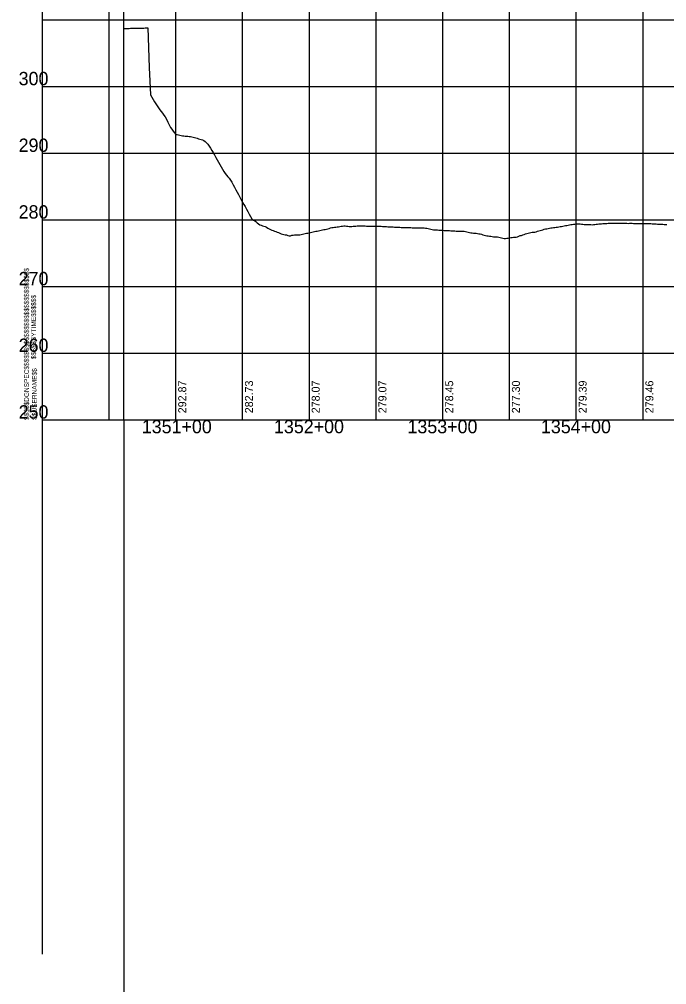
# Model space of a CAD drawing. Extents: x -90830 to 2015517, y -20856 to 836331.
# Drawn here: x 4806 to 5291, y 33228 to 33952 of the extents above; entities that cross this region are included whole.
import ezdxf

# ---------------------------------------------------------------- set-up
doc = ezdxf.new("R2010")
doc.units = 0
for name, color, linetype in [('Level 1', 7, 'Continuous'), ('RD_DDB_ElevTX', 7, 'Continuous'), ('RD_DDB_Profile_EX', 7, 'Continuous'), ('RD_DDB_StaTX', 7, 'Continuous'), ('RD_DDB_StripGrade', 7, 'Continuous'), ('RD_GPK_Profile_Cell', 7, 'Continuous'), ('RD_SHT_MatchLine', 7, 'Continuous')]:
    doc.layers.add(name, color=color, linetype=linetype)

msp = doc.modelspace()

# ---------------------------------------------------------------- linework, layer by layer
at = {"layer": 'Level 1'}
for p, q in [((4823.46, 34151.28), (4823.46, 33651.28)), ((4873.46, 34151.28), (4873.46, 33651.28)), ((4923.46, 34151.28), (4923.46, 33651.28)), ((4973.46, 34151.28), (4973.46, 33651.28)), ((5023.46, 34151.28), (5023.46, 33651.28)), ((5073.46, 34151.28), (5073.46, 33651.28)), ((5123.46, 34151.28), (5123.46, 33651.28)), ((5173.46, 34151.28), (5173.46, 33651.28)), ((5223.46, 34151.28), (5223.46, 33651.28)), ((5273.46, 34151.28), (5273.46, 33651.28)), ((4823.46, 33951.28), (6423.46, 33951.28)), ((4823.46, 33901.28), (6423.46, 33901.28)), ((4823.46, 33851.28), (6423.46, 33851.28)), ((4823.46, 33801.28), (6423.46, 33801.28)), ((4823.46, 33751.28), (6423.46, 33751.28)), ((4823.46, 33701.28), (6423.46, 33701.28)), ((4823.46, 33651.28), (6423.46, 33651.28))]:
    msp.add_line(p, q, dxfattribs=at)
at = {"layer": 'RD_DDB_Profile_EX'}
for points in [[(4884.61, 33944.87), (4885.61, 33944.87), (4886.61, 33944.87), (4887.61, 33944.92), (4888.61, 33944.93), (4889.61, 33944.97), (4890.61, 33945.03), (4891.61, 33945.03), (4892.61, 33945.04), (4893.61, 33945.08), (4894.61, 33945.13), (4895.61, 33945.14), (4896.61, 33945.09), (4897.61, 33945.09), (4898.61, 33945.14), (4899.61, 33945.15), (4900.61, 33945.23), (4901.61, 33945.38), (4902.61, 33945.39), (4903.61, 33915.46), (4904.61, 33895.18), (4905.61, 33893.4), (4906.61, 33891.62), (4907.61, 33889.84), (4908.61, 33888.27), (4909.61, 33886.77), (4910.61, 33885.28), (4911.61, 33883.78), (4912.61, 33882.55), (4913.61, 33881.33), (4914.61, 33879.94), (4915.61, 33878.56), (4916.61, 33876.73), (4917.61, 33874.56), (4918.61, 33872.51), (4919.61, 33870.69), (4920.61, 33869.21), (4921.61, 33867.93), (4922.61, 33866.66), (4923.61, 33865.45), (4924.61, 33865.25), (4925.61, 33865.05), (4926.61, 33864.84), (4927.61, 33864.64), (4928.61, 33864.43), (4929.61, 33864.3), (4930.61, 33864.19), (4931.61, 33864.08), (4932.61, 33863.99), (4933.61, 33863.91), (4934.61, 33863.79), (4935.61, 33863.66), (4936.61, 33863.41), (4937.61, 33863.1), (4938.61, 33862.79), (4939.61, 33862.49), (4940.61, 33862.19), (4941.61, 33861.89), (4942.61, 33861.59), (4943.61, 33861.28), (4944.61, 33860.91), (4945.61, 33859.97), (4946.61, 33859.03), (4947.61, 33858.09), (4948.61, 33856.68), (4949.61, 33855.08), (4950.61, 33853.43), (4951.61, 33851.77), (4952.61, 33850.01), (4953.61, 33848.2), (4954.61, 33846.39), (4955.61, 33844.62), (4956.61, 33842.87), (4957.61, 33841.13), (4958.61, 33839.38), (4959.61, 33837.59), (4960.61, 33836.04), (4961.61, 33834.87), (4962.61, 33833.69), (4963.61, 33832.52), (4964.61, 33831.1), (4965.61, 33829.46), (4966.61, 33827.6), (4967.61, 33825.73), (4968.61, 33823.93), (4969.61, 33822.16), (4970.61, 33820.39), (4971.61, 33818.3), (4972.61, 33816.4), (4973.61, 33814.67), (4974.61, 33812.94), (4975.61, 33811.21), (4976.61, 33809.38), (4977.61, 33807.52), (4978.61, 33805.69), (4979.61, 33803.87), (4980.61, 33802.07), (4981.61, 33801.19), (4982.61, 33800.8), (4983.61, 33799.97), (4984.61, 33799.14)], [(4984.61, 33799.14), (4985.61, 33798.31), (4986.61, 33797.68), (4987.61, 33797.32), (4988.61, 33796.95), (4989.61, 33796.59), (4990.61, 33796.26), (4991.61, 33795.83), (4992.61, 33795.13), (4993.61, 33794.65), (4994.61, 33794.17), (4995.61, 33793.69), (4996.61, 33793.23), (4997.61, 33792.86), (4998.61, 33792.49), (4999.61, 33792.11), (5000.61, 33791.73), (5001.61, 33791.29), (5002.61, 33790.96), (5003.61, 33790.69), (5004.61, 33790.44), (5005.61, 33790.2), (5006.61, 33789.97), (5007.61, 33789.65), (5008.61, 33789.31), (5009.61, 33789.42), (5010.61, 33789.94), (5011.61, 33789.96), (5012.61, 33789.98), (5013.61, 33790.01), (5014.61, 33790.03), (5015.61, 33790.05), (5016.61, 33790.13), (5017.61, 33790.35), (5018.61, 33790.57), (5019.61, 33790.79), (5020.61, 33791.01), (5021.61, 33791.22), (5022.61, 33791.44), (5023.61, 33791.66), (5024.61, 33791.88), (5025.61, 33792.09), (5026.61, 33792.31), (5027.61, 33792.53), (5028.61, 33792.74), (5029.61, 33792.96), (5030.61, 33793.18), (5031.61, 33793.39), (5032.61, 33793.61), (5033.61, 33793.83), (5034.61, 33794.01), (5035.61, 33794.2), (5036.61, 33794.45), (5037.61, 33794.71), (5038.61, 33794.96), (5039.61, 33795.22), (5040.61, 33795.48), (5041.61, 33795.65), (5042.61, 33795.74), (5043.61, 33795.89), (5044.61, 33796.04), (5045.61, 33796.19), (5046.61, 33796.34), (5047.61, 33796.48), (5048.61, 33796.63), (5049.61, 33796.78), (5050.61, 33796.78), (5051.61, 33796.64), (5052.61, 33796.5), (5053.61, 33796.36), (5054.61, 33796.3), (5055.61, 33796.41), (5056.61, 33796.52), (5057.61, 33796.63), (5058.61, 33796.71), (5059.61, 33796.77), (5060.61, 33796.76), (5061.61, 33796.75), (5062.61, 33796.75), (5063.61, 33796.74), (5064.61, 33796.73), (5065.61, 33796.72), (5066.61, 33796.71), (5067.61, 33796.7), (5068.61, 33796.69), (5069.61, 33796.68), (5070.61, 33796.67), (5071.61, 33796.66), (5072.61, 33796.65), (5073.61, 33796.64), (5074.61, 33796.63), (5075.61, 33796.58), (5076.61, 33796.52), (5077.61, 33796.48), (5078.61, 33796.43), (5079.61, 33796.38), (5080.61, 33796.32), (5081.61, 33796.27), (5082.61, 33796.21), (5083.61, 33796.16), (5084.61, 33796.1)], [(5084.61, 33796.1), (5085.61, 33796.05), (5086.61, 33796), (5087.61, 33795.95), (5088.61, 33795.9), (5089.61, 33795.85), (5090.61, 33795.8), (5091.61, 33795.75), (5092.61, 33795.7), (5093.61, 33795.66), (5094.61, 33795.63), (5095.61, 33795.61), (5096.61, 33795.56), (5097.61, 33795.54), (5098.61, 33795.5), (5099.61, 33795.5), (5100.61, 33795.45), (5101.61, 33795.46), (5102.61, 33795.46), (5103.61, 33795.44), (5104.61, 33795.41), (5105.61, 33795.4), (5106.61, 33795.39), (5107.61, 33795.39), (5108.61, 33795.38), (5109.61, 33795.38), (5110.61, 33795.2), (5111.61, 33795.05), (5112.61, 33794.84), (5113.61, 33794.6), (5114.61, 33794.34), (5115.61, 33794.09), (5116.61, 33793.92), (5117.61, 33793.81), (5118.61, 33793.77), (5119.61, 33793.72), (5120.61, 33793.71), (5121.61, 33793.69), (5122.61, 33793.63), (5123.61, 33793.54), (5124.61, 33793.44), (5125.61, 33793.35), (5126.61, 33793.31), (5127.61, 33793.26), (5128.61, 33793.22), (5129.61, 33793.18), (5130.61, 33793.14), (5131.61, 33793.06), (5132.61, 33792.98), (5133.61, 33792.89), (5134.61, 33792.81), (5135.61, 33792.79), (5136.61, 33792.77), (5137.61, 33792.76), (5138.61, 33792.74), (5139.61, 33792.73), (5140.61, 33792.5), (5141.61, 33792.26), (5142.61, 33792.01), (5143.61, 33791.76), (5144.61, 33791.63), (5145.61, 33791.55), (5146.61, 33791.46), (5147.61, 33791.38), (5148.61, 33791.27), (5149.61, 33791.11), (5150.61, 33790.92), (5151.61, 33790.73), (5152.61, 33790.54), (5153.61, 33790.2), (5154.61, 33789.85), (5155.61, 33789.61), (5156.61, 33789.45), (5157.61, 33789.28), (5158.61, 33789.13), (5159.61, 33788.99), (5160.61, 33788.82), (5161.61, 33788.64), (5162.61, 33788.59), (5163.61, 33788.54), (5164.61, 33788.49), (5165.61, 33788.4), (5166.61, 33788.18), (5167.61, 33787.93), (5168.61, 33787.68), (5169.61, 33787.43), (5170.61, 33787.34), (5171.61, 33787.49), (5172.61, 33787.65), (5173.61, 33787.81), (5174.61, 33787.97), (5175.61, 33788.12), (5176.61, 33788.33), (5177.61, 33788.39), (5178.61, 33788.44), (5179.61, 33788.66), (5180.61, 33789.02), (5181.61, 33789.54), (5182.61, 33789.71), (5183.61, 33790.05), (5184.61, 33790.4)], [(5184.61, 33790.4), (5185.61, 33790.74), (5186.61, 33791.09), (5187.61, 33791.43), (5188.61, 33791.7), (5189.61, 33791.89), (5190.61, 33792.05), (5191.61, 33792.11), (5192.61, 33792.18), (5193.61, 33792.45), (5194.61, 33792.73), (5195.61, 33793), (5196.61, 33793.26), (5197.61, 33793.56), (5198.61, 33793.9), (5199.61, 33794.23), (5200.61, 33794.53), (5201.61, 33794.71), (5202.61, 33794.89), (5203.61, 33795.07), (5204.61, 33795.25), (5205.61, 33795.42), (5206.61, 33795.54), (5207.61, 33795.66), (5208.61, 33795.78), (5209.61, 33795.9), (5210.61, 33796.04), (5211.61, 33796.22), (5212.61, 33796.4), (5213.61, 33796.58), (5214.61, 33796.76), (5215.61, 33797), (5216.61, 33797.19), (5217.61, 33797.37), (5218.61, 33797.56), (5219.61, 33797.74), (5220.61, 33797.88), (5221.61, 33798.01), (5222.61, 33798.14), (5223.61, 33798.27), (5224.61, 33798.34), (5225.61, 33798.33), (5226.61, 33798.24), (5227.61, 33798.15), (5228.61, 33798.05), (5229.61, 33797.96), (5230.61, 33797.87), (5231.61, 33797.85), (5232.61, 33797.82), (5233.61, 33797.79), (5234.61, 33797.72), (5235.61, 33797.65), (5236.61, 33797.79), (5237.61, 33797.92), (5238.61, 33798.03), (5239.61, 33798.13), (5240.61, 33798.23), (5241.61, 33798.32), (5242.61, 33798.4), (5243.61, 33798.48), (5244.61, 33798.56), (5245.61, 33798.63), (5246.61, 33798.71), (5247.61, 33798.79), (5248.61, 33798.87), (5249.61, 33798.95), (5250.61, 33798.95), (5251.61, 33798.94), (5252.61, 33798.92), (5253.61, 33798.9), (5254.61, 33798.89), (5255.61, 33798.87), (5256.61, 33798.85), (5257.61, 33798.84), (5258.61, 33798.82), (5259.61, 33798.79), (5260.61, 33798.76), (5261.61, 33798.73), (5262.61, 33798.69), (5263.61, 33798.76), (5264.61, 33798.74), (5265.61, 33798.72), (5266.61, 33798.71), (5267.61, 33798.69), (5268.61, 33798.67), (5269.61, 33798.66), (5270.61, 33798.64), (5271.61, 33798.62), (5272.61, 33798.61), (5273.61, 33798.59), (5274.61, 33798.58), (5275.61, 33798.56), (5276.61, 33798.54), (5277.61, 33798.53), (5278.61, 33798.51), (5279.61, 33798.47), (5280.61, 33798.42), (5281.61, 33798.37), (5282.61, 33798.33), (5283.61, 33798.26), (5284.61, 33798.2)], [(5284.61, 33798.2), (5285.61, 33798.15), (5286.61, 33798.1), (5287.61, 33798.05), (5288.61, 33798), (5289.61, 33797.95), (5290.61, 33797.9), (5291.61, 33797.85)]]:
    msp.add_lwpolyline(points, dxfattribs=at)
at = {"layer": 'RD_GPK_Profile_Cell'}
for q in [(4884.61, 34901.28), (7384.61, 33651.28), (4884.61, 32401.28)]:
    msp.add_line((4884.61, 33651.28), q, dxfattribs=at)
at = {"layer": 'RD_SHT_MatchLine'}
for p, q in [((4823.46, 33651.28), (4823.46, 33250.63)), ((4884.61, 33651.28), (4884.61, 33250.63))]:
    msp.add_line(p, q, dxfattribs=at)

# ---------------------------------------------------------------- texts
at = {"layer": 'Level 1'}
for s, p in [('$$$$$DGNSPEC$$$$$$$$$$$$$$$$$$$$$$$$$$$$', (4813.56, 33651.23)), ('$$$$$SYTIME$$$$$$', (4818.86, 33696.83)), ('$$USERNAME$$', (4819.46, 33651.38))]:
    msp.add_text(s, height=3.5436, rotation=90, dxfattribs=at).set_placement(p)
at = {"layer": 'RD_DDB_ElevTX'}
for s, p in [('300', (4805.9, 33902.28)), ('290', (4805.9, 33852.28)), ('280', (4805.9, 33802.28)), ('270', (4805.9, 33752.28)), ('260', (4805.9, 33702.28)), ('250', (4805.9, 33652.28))]:
    msp.add_text(s, height=10, dxfattribs=at).set_placement(p)
at = {"layer": 'RD_DDB_StaTX'}
for s, p in [('1351+00', (4898.17, 33641.28)), ('1352+00', (4997.21, 33641.28)), ('1353+00', (5097.21, 33641.28)), ('1354+00', (5197.21, 33641.28))]:
    msp.add_text(s, height=10, dxfattribs=at).set_placement(p)
at = {"layer": 'RD_DDB_StripGrade'}
for s, p in [('292.87', (4931.46, 33656.28)), ('282.73', (4981.46, 33656.28)), ('278.07', (5031.46, 33656.28)), ('279.07', (5081.46, 33656.28)), ('278.45', (5131.46, 33656.28)), ('277.30', (5181.46, 33656.28)), ('279.39', (5231.46, 33656.28)), ('279.46', (5281.46, 33656.28))]:
    msp.add_text(s, height=6, rotation=90, dxfattribs=at).set_placement(p)

doc.saveas('drawing.dxf')
